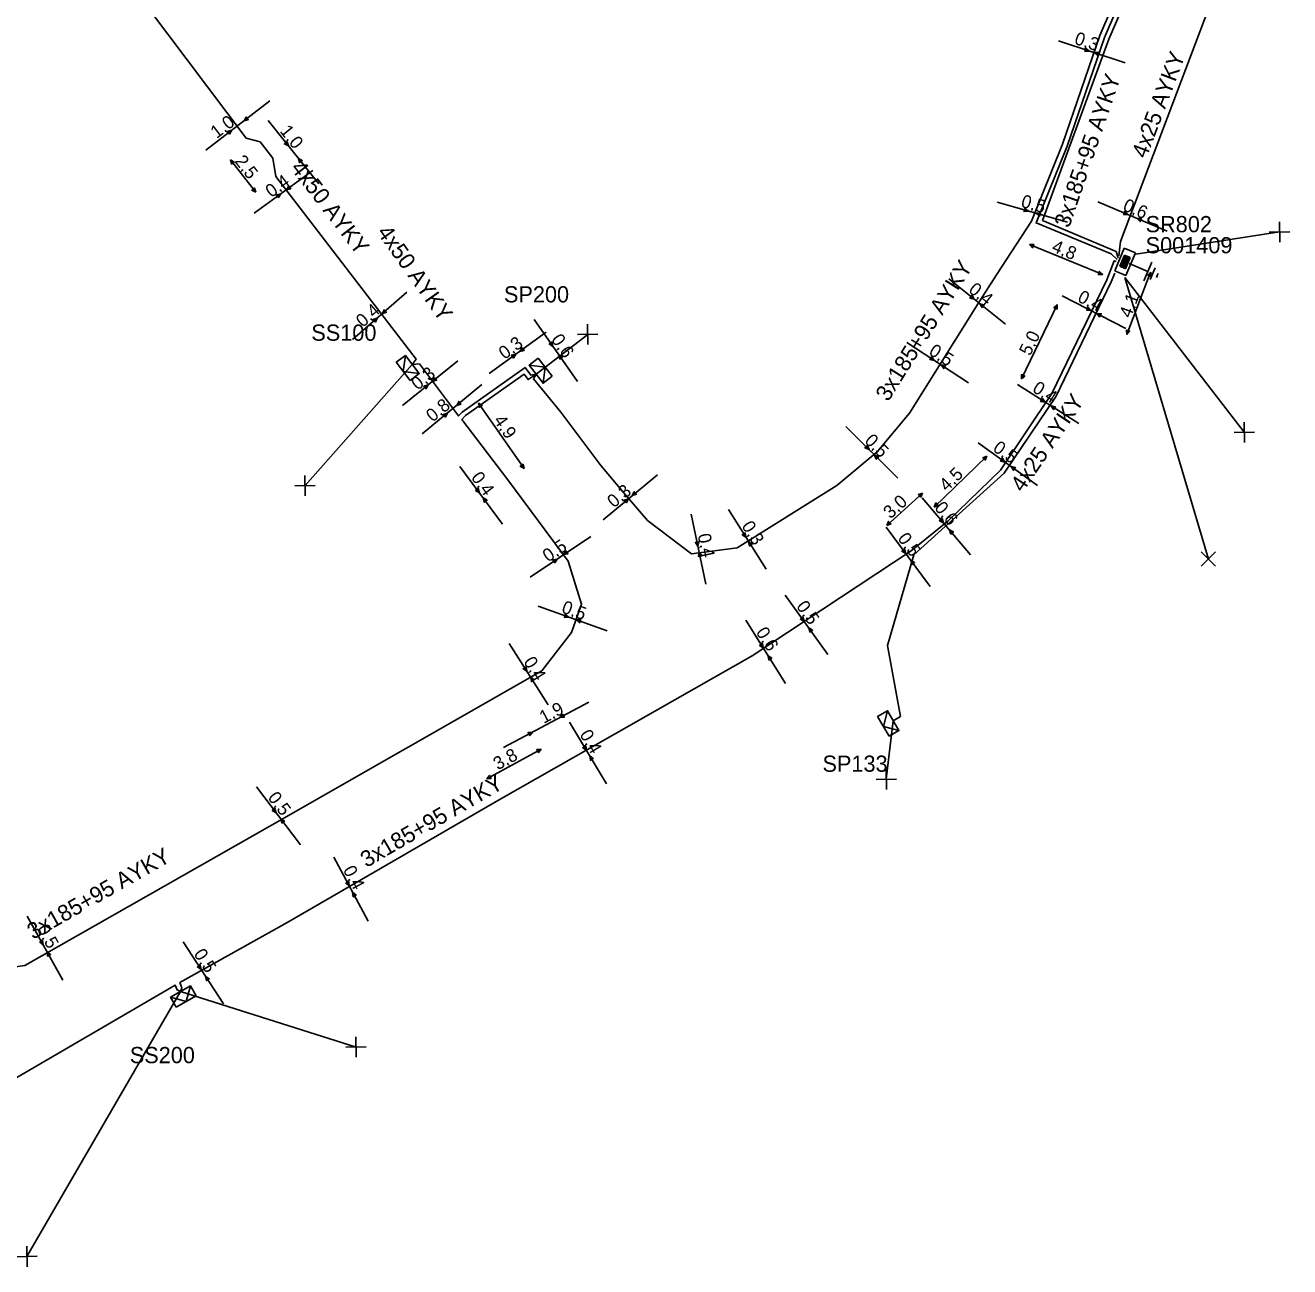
# Model space of a CAD drawing. Extents: x -762500 to -761285, y -1155006 to -1154135.
# Drawn here: x -761689 to -761611.5, y -1154654.9 to -1154578.8 of the extents above; entities that cross this region are included whole.
import ezdxf

# ---------------------------------------------------------------- set-up
doc = ezdxf.new("R2010")
doc.units = 0
for name, color, linetype in [('Vrstva 15', 7, 'Continuous'), ('Vrstva 28', 7, 'Continuous'), ('Vrstva 29', 7, 'Continuous'), ('Vrstva 30', 7, 'Continuous'), ('Vrstva 31', 7, 'Continuous'), ('Vrstva 33', 7, 'Continuous'), ('Vrstva 34', 7, 'Continuous'), ('Vrstva 40', 7, 'Continuous'), ('Vrstva 5', 7, 'Continuous'), ('Vrstva 59', 7, 'Continuous'), ('Vrstva 6', 7, 'Continuous')]:
    doc.layers.add(name, color=color, linetype=linetype)

msp = doc.modelspace()

# ---------------------------------------------------------------- linework, layer by layer
at = {"layer": 'Vrstva 15'}
for points in [[(-761621.359, -1154593.386), (-761620.208, -1154593.874)], [(-761619.964, -1154593.299), (-761620.452, -1154594.45)], [(-761619.773, -1154593.642), (-761620.08, -1154594.367)], [(-761619.633, -1154594.119), (-761619.683, -1154594.236)], [(-761619.581, -1154593.996), (-761619.633, -1154594.119)]]:
    msp.add_lwpolyline(points, dxfattribs=at)
at = {"layer": 'Vrstva 28'}
for points in [[(-761621.659, -1154592.446), (-761622.245, -1154593.827)], [(-761621.641, -1154592.871), (-761621.931, -1154593.556)], [(-761621.616, -1154592.933), (-761621.869, -1154593.531)], [(-761621.59, -1154592.995), (-761621.807, -1154593.506)], [(-761621.565, -1154593.057), (-761621.745, -1154593.481)], [(-761621.686, -1154593.462), (-761621.538, -1154593.114)], [(-761620.969, -1154592.739), (-761621.659, -1154592.446)], [(-761621.658, -1154593.518), (-761621.478, -1154593.094)], [(-761621.293, -1154593.019), (-761621.641, -1154592.871)], [(-761621.633, -1154593.58), (-761621.417, -1154593.069)], [(-761621.355, -1154593.044), (-761621.616, -1154592.933)], [(-761621.608, -1154593.642), (-761621.355, -1154593.044)], [(-761621.417, -1154593.069), (-761621.59, -1154592.995)], [(-761621.583, -1154593.704), (-761621.293, -1154593.019)], [(-761621.478, -1154593.094), (-761621.565, -1154593.057)], [(-761621.555, -1154594.12), (-761620.969, -1154592.739)], [(-761622.245, -1154593.827), (-761621.555, -1154594.12)], [(-761621.931, -1154593.556), (-761621.583, -1154593.704)], [(-761621.869, -1154593.531), (-761621.608, -1154593.642)], [(-761621.807, -1154593.506), (-761621.633, -1154593.58)], [(-761621.745, -1154593.481), (-761621.658, -1154593.518)]]:
    msp.add_lwpolyline(points, dxfattribs=at)
at = {"layer": 'Vrstva 31'}
for points in [[(-761666.292, -1154599.44), (-761665.733, -1154599.019), (-761664.891, -1154600.137), (-761665.45, -1154600.558)], [(-761665.871, -1154599.999), (-761665.733, -1154599.019)], [(-761656.735, -1154600.293), (-761657.287, -1154600.724), (-761658.149, -1154599.62), (-761657.597, -1154599.19)], [(-761656.735, -1154600.293), (-761657.597, -1154599.19)], [(-761666.292, -1154599.44), (-761665.45, -1154600.558)], [(-761665.871, -1154599.999), (-761664.891, -1154600.137)], [(-761657.166, -1154599.741), (-761658.149, -1154599.62)], [(-761657.166, -1154599.741), (-761657.287, -1154600.724)], [(-761636.778, -1154621.151), (-761636.171, -1154620.801), (-761635.471, -1154622.014), (-761636.078, -1154622.364)], [(-761636.428, -1154621.757), (-761636.171, -1154620.801)], [(-761636.778, -1154621.151), (-761636.078, -1154622.364)], [(-761636.428, -1154621.757), (-761635.471, -1154622.014)], [(-761679.778, -1154638.968), (-761680.128, -1154638.362), (-761678.916, -1154637.662), (-761678.566, -1154638.268)], [(-761679.172, -1154638.618), (-761678.916, -1154637.662)], [(-761679.172, -1154638.618), (-761680.128, -1154638.362)], [(-761679.778, -1154638.968), (-761678.566, -1154638.268)]]:
    msp.add_lwpolyline(points, dxfattribs=at)
at = {"layer": 'Vrstva 34'}
for points in [[(-761612.129, -1154592.075), (-761612.151, -1154590.825)], [(-761612.765, -1154591.461), (-761611.515, -1154591.439)], [(-761655.175, -1154597.741), (-761653.925, -1154597.719)], [(-761654.539, -1154598.355), (-761654.561, -1154597.105)], [(-761614.289, -1154604.355), (-761614.311, -1154603.105)], [(-761614.925, -1154603.741), (-761613.675, -1154603.719)], [(-761672.505, -1154607.011), (-761671.255, -1154606.989)], [(-761671.869, -1154607.625), (-761671.891, -1154606.375)], [(-761616.942, -1154611.058), (-761616.058, -1154611.942)], [(-761616.942, -1154611.942), (-761616.058, -1154611.058)], [(-761636.239, -1154625.625), (-761636.261, -1154624.375)], [(-761636.875, -1154625.011), (-761635.625, -1154624.989)], [(-761668.749, -1154642.035), (-761668.771, -1154640.785)], [(-761669.385, -1154641.421), (-761668.135, -1154641.399)], [(-761688.929, -1154654.875), (-761688.951, -1154653.625)], [(-761689.565, -1154654.261), (-761688.315, -1154654.239)]]:
    msp.add_lwpolyline(points, dxfattribs=at)
at = {"layer": 'Vrstva 40'}
for points in [[(-761621.6, -1154581.09), (-761625.7, -1154579.73)], [(-761674.04, -1154583.42), (-761677.97, -1154586.43)], [(-761671.04, -1154588.51), (-761674.15, -1154584.62)], [(-761674.91, -1154589.02), (-761676.46, -1154587.04)], [(-761675, -1154590.29), (-761671.4, -1154587.69)], [(-761629.46, -1154589.62), (-761625.13, -1154590.86)], [(-761623.27, -1154589.6), (-761619.03, -1154591.41)], [(-761622.98, -1154594.06), (-761627.47, -1154592.23)], [(-761620.04, -1154593.91), (-761621.5, -1154597.73)], [(-761632.42, -1154594.32), (-761628.95, -1154597.1)], [(-761665.64, -1154595.15), (-761668.97, -1154598.04)], [(-761621.56, -1154597.37), (-761625.47, -1154595.36)], [(-761625.77, -1154595.91), (-761627.96, -1154600.46)], [(-761657.83, -1154596.82), (-761655.19, -1154600.62)], [(-761660.59, -1154600.13), (-761657.1, -1154597.6)], [(-761634.99, -1154598.23), (-761631.2, -1154600.69)], [(-761665.9, -1154602.09), (-761662.52, -1154599.36)], [(-761661.04, -1154600.8), (-761664.71, -1154603.83)], [(-761624.45, -1154603.19), (-761628.21, -1154600.81)], [(-761658.46, -1154605.95), (-761661.25, -1154601.94)], [(-761638.72, -1154603.37), (-761635.55, -1154606.54)], [(-761626.97, -1154607), (-761630.61, -1154604.38)], [(-761633.31, -1154608.31), (-761630.08, -1154605.19)], [(-761659.77, -1154609.37), (-761662.39, -1154605.83)], [(-761650.28, -1154606.33), (-761653.6, -1154609.09)], [(-761636.22, -1154609.44), (-761634.03, -1154607.46)], [(-761631.08, -1154611.25), (-761634.04, -1154607.74)], [(-761645.93, -1154608.47), (-761643.62, -1154612.12)], [(-761648.21, -1154608.74), (-761647.31, -1154613.04)], [(-761658.09, -1154612.62), (-761654.37, -1154610.11)], [(-761633.56, -1154613.19), (-761636.25, -1154609.55)], [(-761639.83, -1154617.35), (-761642.45, -1154613.71)], [(-761657.6, -1154614.38), (-761653.37, -1154615.91)], [(-761642.42, -1154619.12), (-761644.87, -1154615.25)], [(-761659.36, -1154616.68), (-761656.98, -1154620.44)], [(-761659.71, -1154623.05), (-761654.49, -1154620.28)], [(-761653.4, -1154625.28), (-761655.67, -1154621.5)], [(-761660.74, -1154624.97), (-761657.41, -1154623.15)], [(-761672.16, -1154629.02), (-761674.87, -1154625.46)], [(-761668.02, -1154633.69), (-761670.13, -1154629.78)], [(-761686.73, -1154637.32), (-761688.92, -1154633.39)], [(-761676.89, -1154638.76), (-761679.35, -1154634.97)]]:
    msp.add_lwpolyline(points, dxfattribs=at)
for points in [[(-761623.798, -1154580.361), (-761624.066, -1154580.384), (-761624.002, -1154580.185)], [(-761623.502, -1154580.459), (-761623.234, -1154580.436), (-761623.298, -1154580.635)], [(-761675.622, -1154584.641), (-761675.491, -1154584.406), (-761675.362, -1154584.571)], [(-761676.378, -1154585.218), (-761676.51, -1154585.454), (-761676.638, -1154585.289)], [(-761672.908, -1154586.182), (-761673.146, -1154586.054), (-761672.983, -1154585.923)], [(-761672.291, -1154586.948), (-761672.054, -1154587.075), (-761672.216, -1154587.207)], [(-761676.462, -1154587.037), (-761676.224, -1154587.165), (-761676.386, -1154587.296)], [(-761674.909, -1154589.022), (-761675.147, -1154588.895), (-761674.984, -1154588.763)], [(-761673.378, -1154589.119), (-761673.518, -1154589.349), (-761673.64, -1154589.18)], [(-761673.022, -1154588.861), (-761672.882, -1154588.631), (-761672.76, -1154588.8)], [(-761627.538, -1154590.171), (-761627.805, -1154590.207), (-761627.751, -1154590.006)], [(-761627.052, -1154590.309), (-761626.785, -1154590.273), (-761626.839, -1154590.474)], [(-761621.428, -1154590.381), (-761621.697, -1154590.38), (-761621.616, -1154590.187)], [(-761620.873, -1154590.619), (-761620.603, -1154590.62), (-761620.685, -1154590.812)], [(-761627.473, -1154592.229), (-761627.203, -1154592.225), (-761627.281, -1154592.419)], [(-761622.978, -1154594.061), (-761623.248, -1154594.065), (-761623.169, -1154593.871)], [(-761620.039, -1154593.908), (-761620.026, -1154594.177), (-761620.222, -1154594.105)], [(-761630.858, -1154595.572), (-761631.118, -1154595.501), (-761630.99, -1154595.336)], [(-761667.152, -1154596.462), (-761667.037, -1154596.218), (-761666.897, -1154596.373)], [(-761630.512, -1154595.848), (-761630.252, -1154595.919), (-761630.38, -1154596.084)], [(-761625.769, -1154595.908), (-761625.779, -1154596.178), (-761625.969, -1154596.089)], [(-761623.688, -1154596.271), (-761623.957, -1154596.252), (-761623.862, -1154596.065)], [(-761667.458, -1154596.728), (-761667.573, -1154596.972), (-761667.713, -1154596.817)], [(-761623.342, -1154596.449), (-761623.073, -1154596.468), (-761623.168, -1154596.655)], [(-761621.502, -1154597.732), (-761621.515, -1154597.463), (-761621.318, -1154597.534)], [(-761658.722, -1154598.781), (-761658.582, -1154598.55), (-761658.459, -1154598.72)], [(-761656.689, -1154598.463), (-761656.917, -1154598.319), (-761656.746, -1154598.199)], [(-761658.968, -1154598.949), (-761659.107, -1154599.179), (-761659.23, -1154599.01)], [(-761656.331, -1154598.978), (-761656.103, -1154599.122), (-761656.274, -1154599.242)], [(-761633.308, -1154599.322), (-761633.573, -1154599.274), (-761633.46, -1154599.099)], [(-761632.882, -1154599.598), (-761632.617, -1154599.646), (-761632.73, -1154599.821)], [(-761664.338, -1154600.829), (-761664.465, -1154601.066), (-761664.597, -1154600.904)], [(-761664.082, -1154600.621), (-761663.955, -1154600.384), (-761663.823, -1154600.546)], [(-761627.961, -1154600.463), (-761627.951, -1154600.193), (-761627.761, -1154600.281)], [(-761626.518, -1154601.882), (-761626.784, -1154601.838), (-761626.673, -1154601.661)], [(-761662.582, -1154602.082), (-761662.459, -1154601.842), (-761662.325, -1154602.002)], [(-761661.252, -1154601.938), (-761661.024, -1154602.081), (-761661.195, -1154602.201)], [(-761626.142, -1154602.118), (-761625.876, -1154602.162), (-761625.987, -1154602.339)], [(-761663.158, -1154602.558), (-761663.282, -1154602.798), (-761663.416, -1154602.638)], [(-761637.308, -1154604.782), (-761637.558, -1154604.68), (-761637.41, -1154604.532)], [(-761636.962, -1154605.128), (-761636.712, -1154605.23), (-761636.86, -1154605.378)], [(-761630.078, -1154605.188), (-761630.18, -1154605.438), (-761630.328, -1154605.29)], [(-761628.978, -1154605.552), (-761629.242, -1154605.495), (-761629.122, -1154605.323)], [(-761658.459, -1154605.952), (-761658.687, -1154605.808), (-761658.516, -1154605.689)], [(-761628.592, -1154605.828), (-761628.328, -1154605.885), (-761628.448, -1154606.057)], [(-761661.198, -1154607.433), (-761661.431, -1154607.297), (-761661.264, -1154607.171)], [(-761660.962, -1154607.758), (-761660.729, -1154607.894), (-761660.896, -1154608.02)], [(-761652.058, -1154607.809), (-761652.181, -1154608.048), (-761652.316, -1154607.888)], [(-761651.822, -1154607.611), (-761651.699, -1154607.372), (-761651.564, -1154607.532)], [(-761634.028, -1154607.458), (-761634.138, -1154607.704), (-761634.281, -1154607.551)], [(-761633.312, -1154608.312), (-761633.21, -1154608.062), (-761633.062, -1154608.21)], [(-761636.222, -1154609.442), (-761636.111, -1154609.196), (-761635.969, -1154609.348)], [(-761632.749, -1154609.272), (-761632.99, -1154609.153), (-761632.833, -1154609.016)], [(-761644.859, -1154610.162), (-761645.082, -1154610.011), (-761644.907, -1154609.897)], [(-761632.372, -1154609.718), (-761632.13, -1154609.837), (-761632.287, -1154609.974)], [(-761656.032, -1154611.231), (-761655.889, -1154611.003), (-761655.769, -1154611.174)], [(-761647.8, -1154610.703), (-761647.954, -1154610.481), (-761647.749, -1154610.438)], [(-761644.691, -1154610.428), (-761644.468, -1154610.579), (-761644.643, -1154610.693)], [(-761635.059, -1154611.162), (-761635.292, -1154611.026), (-761635.125, -1154610.901)], [(-761656.428, -1154611.499), (-761656.571, -1154611.727), (-761656.691, -1154611.556)], [(-761647.72, -1154611.077), (-761647.566, -1154611.299), (-761647.771, -1154611.342)], [(-761634.751, -1154611.578), (-761634.518, -1154611.714), (-761634.685, -1154611.839)], [(-761655.718, -1154615.061), (-761655.987, -1154615.079), (-761655.919, -1154614.881)], [(-761655.252, -1154615.229), (-761654.983, -1154615.211), (-761655.051, -1154615.409)], [(-761641.279, -1154615.332), (-761641.509, -1154615.192), (-761641.34, -1154615.07)], [(-761641.001, -1154615.718), (-761640.771, -1154615.858), (-761640.94, -1154615.98)], [(-761643.799, -1154616.942), (-761644.022, -1154616.791), (-761643.847, -1154616.677)], [(-761643.491, -1154617.428), (-761643.268, -1154617.579), (-761643.443, -1154617.693)], [(-761658.289, -1154618.372), (-761658.512, -1154618.221), (-761658.337, -1154618.107)], [(-761658.051, -1154618.748), (-761657.828, -1154618.899), (-761658.003, -1154619.013)], [(-761656.262, -1154621.221), (-761656.092, -1154621.012), (-761655.994, -1154621.197)], [(-761657.938, -1154622.109), (-761658.108, -1154622.318), (-761658.206, -1154622.133)], [(-761657.407, -1154623.149), (-761657.574, -1154623.361), (-761657.675, -1154623.178)], [(-761654.639, -1154623.222), (-761654.857, -1154623.063), (-761654.677, -1154622.955)], [(-761654.431, -1154623.568), (-761654.214, -1154623.727), (-761654.393, -1154623.835)], [(-761660.742, -1154624.971), (-761660.575, -1154624.759), (-761660.474, -1154624.942)], [(-761673.659, -1154627.052), (-761673.894, -1154626.921), (-761673.729, -1154626.792)], [(-761673.371, -1154627.428), (-761673.136, -1154627.559), (-761673.301, -1154627.688)], [(-761669.179, -1154631.542), (-761669.391, -1154631.376), (-761669.208, -1154631.274)], [(-761668.971, -1154631.928), (-761668.759, -1154632.094), (-761668.942, -1154632.196)], [(-761687.939, -1154635.142), (-761688.154, -1154634.979), (-761687.973, -1154634.875)], [(-761687.701, -1154635.568), (-761687.486, -1154635.731), (-761687.667, -1154635.835)], [(-761678.259, -1154636.652), (-761678.484, -1154636.505), (-761678.311, -1154636.388)], [(-761677.981, -1154637.078), (-761677.756, -1154637.225), (-761677.929, -1154637.342)]]:
    msp.add_lwpolyline(points, close=True, dxfattribs=at)
at = {"layer": 'Vrstva 5'}
for points in [[(-761622.04, -1154593.03), (-761622.16, -1154592.65), (-761626.67, -1154590.74), (-761622.6, -1154579.64), (-761621.66, -1154577.46), (-761621.79, -1154577.06), (-761620.62, -1154574.05), (-761619.85, -1154572.37), (-761637.13, -1154552.32), (-761648.69, -1154536.07), (-761652.41, -1154536.27), (-761659.5, -1154540.99), (-761660.72, -1154540.01), (-761661.12, -1154539.06), (-761661.14, -1154538.24)], [(-761621.99, -1154592.91), (-761621.89, -1154592.03), (-761613.6, -1154570.1), (-761612.91, -1154569.21)], [(-761625.23, -1154577.4), (-761625.15, -1154577.15), (-761624.54, -1154576.72), (-761622.06, -1154577.64), (-761622.18, -1154577.91), (-761622.88, -1154579.53), (-761625.16, -1154586.19), (-761627.06, -1154590.9), (-761622.47, -1154592.8), (-761622.09, -1154593.15)], [(-761625.23, -1154577.4), (-761624.99, -1154577.39), (-761624.5, -1154577.05), (-761622.46, -1154577.79), (-761623.16, -1154579.42), (-761625.44, -1154586.08), (-761627.34, -1154590.79), (-761629.49, -1154594.07), (-761630.52, -1154595.68), (-761634.83, -1154602.56), (-761636.8, -1154604.93), (-761639.28, -1154606.99), (-761645.39, -1154610.82), (-761648.2, -1154611.18), (-761650.88, -1154609.13), (-761652.37, -1154607.42), (-761653.76, -1154605.77), (-761656.21, -1154602.49), (-761657.87, -1154600.45), (-761657.72, -1154600.17)], [(-761657.72, -1154600.17), (-761658.05, -1154600.22), (-761658.39, -1154599.75), (-761662.25, -1154602.49), (-761662.48, -1154602.73), (-761664.87, -1154599.53), (-761665.31, -1154599.58), (-761665.08, -1154599.25), (-761673.68, -1154588.06), (-761673.86, -1154586.92), (-761674.64, -1154585.92), (-761675.5, -1154585.7), (-761681.49, -1154577.75)], [(-761704.25, -1154651.83), (-761704.28, -1154651.79), (-761704.43, -1154651.59), (-761690.54, -1154643.85), (-761679.84, -1154637.62), (-761679.72, -1154637.91), (-761679.52, -1154638.01), (-761679.44, -1154637.79), (-761679.56, -1154637.46), (-761672.93, -1154633.76), (-761660.03, -1154626.27), (-761644.47, -1154617.44), (-761634.73, -1154611), (-761632.48, -1154609.17), (-761629.25, -1154606.05), (-761626.09, -1154601.36), (-761622.73, -1154594.39), (-761622.27, -1154593.22), (-761622.15, -1154593.27)], [(-761622.24, -1154593.97), (-761622.46, -1154594.51), (-761625.83, -1154601.51), (-761629.02, -1154606.24), (-761634.55, -1154611.24), (-761636.18, -1154616.79), (-761635.38, -1154621.15), (-761635.82, -1154621.41)], [(-761657.72, -1154600.17), (-761658.21, -1154600.5), (-761658.46, -1154600.16), (-761662.05, -1154602.71), (-761662.27, -1154602.94), (-761659.45, -1154606.64), (-761655.76, -1154611.62), (-761654.94, -1154614.27), (-761655.55, -1154616.01), (-761657.36, -1154618.35), (-761674.05, -1154627.87), (-761689.06, -1154636.42), (-761691.47, -1154636.76), (-761693.9, -1154636.43), (-761696.1, -1154635.07), (-761698.62, -1154631.94), (-761699.01, -1154632.1), (-761702.49, -1154634.66), (-761702.64, -1154634.96), (-761702.95, -1154635.12)]]:
    msp.add_lwpolyline(points, dxfattribs=at)
at = {"layer": 'Vrstva 59'}
for points in [[(-761620.94, -1154592.82), (-761612.14, -1154591.45)], [(-761621.62, -1154594.24), (-761614.3, -1154603.73)], [(-761621.62, -1154594.24), (-761616.5, -1154611.5)], [(-761657.72, -1154600.17), (-761654.55, -1154597.73)], [(-761665.31, -1154599.58), (-761671.88, -1154607)], [(-761635.82, -1154621.41), (-761636.25, -1154625)], [(-761679.52, -1154638.01), (-761688.94, -1154654.25)], [(-761679.52, -1154638.01), (-761668.76, -1154641.41)]]:
    msp.add_lwpolyline(points, dxfattribs=at)

# ---------------------------------------------------------------- texts
at = {"layer": 'Vrstva 29'}
msp.add_text('S001409', height=0.9943, dxfattribs=at).set_placement((-761620.35, -1154592.76))
at = {"layer": 'Vrstva 30'}
msp.add_text('SR802', height=0.9943, dxfattribs=at).set_placement((-761620.35, -1154591.47))
at = {"layer": 'Vrstva 33'}
for s, p in [('SP200', (-761659.69, -1154595.77)), ('SS100', (-761671.5, -1154598.12)), ('SP133', (-761640.16, -1154624.54)), ('SS200', (-761682.63, -1154642.4))]:
    msp.add_text(s, height=0.9943, dxfattribs=at).set_placement(p)
at = {"layer": 'Vrstva 40'}
for s, rotation, p in [('0,3', 341.56505, (-761624.77, -1154579.91)), ('1,0', 37.41694, (-761677.3, -1154585.76)), ('1,0', 308.66259, (-761673.47, -1154585.28)), ('2,5', 308.00436, (-761676.24, -1154587.12)), ('0,4', 35.8381, (-761673.95, -1154589.38)), ('0,5', 344.05815, (-761628.04, -1154589.9)), ('0,6', 336.79766, (-761621.8, -1154590.1)), ('4,8', 337.82535, (-761626.16, -1154592.63)), ('0,4', 321.34172, (-761631.26, -1154595.09)), ('0,4', 332.77795, (-761624.58, -1154595.68)), ('4,1', 69.10211, (-761621.26, -1154596.77)), ('0,4', 41.05663, (-761668.34, -1154597.34)), ('0,6', 304.69472, (-761656.83, -1154598.04)), ('5,0', 64.29769, (-761627.43, -1154599.09)), ('0,3', 35.95334, (-761659.65, -1154599.3)), ('0,5', 326.93498, (-761633.7, -1154598.92)), ('0,3', 38.92794, (-761664.98, -1154601.19)), ('0,4', 327.72913, (-761627.35, -1154601.21)), ('0,8', 39.53886, (-761664.06, -1154603.14)), ('4,9', 304.81193, (-761660.36, -1154603)), ('0,5', 315, (-761637.63, -1154604.3)), ('0,5', 324.33081, (-761629.77, -1154604.83)), ('0,4', 306.6046, (-761661.74, -1154606.51)), ('4,5', 44.00754, (-761632.54, -1154607.4)), ('0,3', 39.80916, (-761652.95, -1154608.4)), ('3,0', 42.18496, (-761635.99, -1154609.07)), ('0,6', 310.18264, (-761633.34, -1154608.38)), ('0,3', 302.19746, (-761645.15, -1154609.47)), ('0,4', 281.89389, (-761647.82, -1154610.02)), ('0,5', 306.42523, (-761635.59, -1154610.24)), ('0,5', 34.02236, (-761656.98, -1154611.72)), ('0,5', 340.11571, (-761656.21, -1154614.76)), ('0,5', 305.6766, (-761641.8, -1154614.4)), ('0,6', 302.31766, (-761644.27, -1154615.98)), ('0,4', 302.27911, (-761658.52, -1154617.79)), ('1,9', 27.98618, (-761657.25, -1154621.61)), ('0,4', 300.96008, (-761655.08, -1154622.25)), ('3,8', 28.65854, (-761660.07, -1154624.46)), ('0,5', 307.35184, (-761674.21, -1154626.13)), ('0,4', 298.29875, (-761669.58, -1154630.55)), ('0,5', 299.16346, (-761688.35, -1154634.16)), ('0,5', 303.06502, (-761678.74, -1154635.7))]:
    msp.add_text(s, height=0.7954, rotation=rotation, dxfattribs=at).set_placement(p)
at = {"layer": 'Vrstva 6'}
for s, height, rotation, p in [('4x25 AYKY', 0.9943, 69.29919, (-761620.31, -1154587)), ('3x185+95 AYKY', 0.99429, 71.10154, (-761625.04, -1154591.25)), ('4x50 AYKY', 0.9943, 307.53716, (-761672.81, -1154587.55)), ('4x50 AYKY', 0.9943, 305.37297, (-761667.51, -1154591.48)), ('3x185+95 AYKY', 0.99429, 57.93477, (-761636.13, -1154601.9)), ('4x25 AYKY', 0.9943, 56.02599, (-761627.88, -1154607.46)), ('3x185+95 AYKY', 0.99429, 30.14031, (-761668.12, -1154630.44)), ('3x185+95 AYKY', 0.99429, 29.66671, (-761688.56, -1154634.85))]:
    msp.add_text(s, height=height, rotation=rotation, dxfattribs=at).set_placement(p)

doc.saveas('drawing.dxf')
